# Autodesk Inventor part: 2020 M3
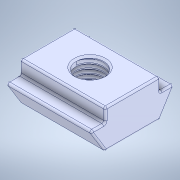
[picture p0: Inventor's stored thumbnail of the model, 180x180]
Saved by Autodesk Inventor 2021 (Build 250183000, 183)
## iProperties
Created: 2026-02
Part Number: 2020 M3
Material: Generic
Description: STEP AP214
Document SubType Name: Modeling
Designer: hp
Density: 1 g/cm^3
Appearance: Default
Title: 2020 M3.STEP
Revision Number: HERHANGÝ
Sending System: SolidWorks 2020
Preprocessor: SwSTEP 2.0
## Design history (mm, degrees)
feature "Radyus3"
body "Solid1"
